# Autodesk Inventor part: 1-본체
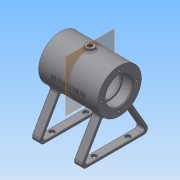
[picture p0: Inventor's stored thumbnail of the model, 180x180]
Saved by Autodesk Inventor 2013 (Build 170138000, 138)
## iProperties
Created: 2016-03
Part Number: 1-본체
Material: Generic
Document SubType Name: Modeling
Designer: Administrator
Density: 1 g/cm^3
Author: Administrator
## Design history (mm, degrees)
sketch "스케치1"
  geometry: C1 r 26 at (0, 0); 1 further point
  constraints: 1 centre point, 1 coincident
  dimensions: "d0" = 52 diameter of C1
extrude "돌출1" new body sketch "스케치1" distance "d2" = 70; taper "d3" = 0 deg
sketch "스케치2"
  geometry: C1 r 26 at (0, 0) reference; C2 r 16 at (0, 0)
  constraints: 1 centre point, 1 coincident
  dimensions: "d4" = 32 diameter of C2
extrude "돌출2" cut sketch "스케치2" distance "d6" = 12; taper "d7" = 0 deg
sketch "스케치3"
  geometry: C1 r 26 at (0, 0) reference; C2 r 16 at (0, 0)
  constraints: 1 centre point, 1 coincident
  dimensions: "d8" = 32 diameter of C2
extrude "돌출3" cut sketch "스케치3" distance "d10" = 12; taper "d11" = 0 deg
sketch "스케치4"
  geometry: C1 r 16 at (0, 0) reference; C2 r 14 at (0, 0)
  constraints: 1 centre point, 1 coincident
  dimensions: "d12" = 28 diameter of C2
extrude "돌출4" cut sketch "스케치4" distance "d14" = 2; taper "d15" = 0 deg
sketch "스케치5"
  geometry: C1 r 16 at (0, 0) reference; C2 r 14 at (0, 0)
  constraints: 1 centre point, 1 coincident
  dimensions: "d16" = 28 diameter of C2
extrude "돌출5" cut sketch "스케치5" distance "d18" = 2; taper "d19" = 0 deg
sketch "스케치6"
  geometry: C1 r 14 at (0, 0) reference; C2 r 21 at (0, 0)
  constraints: 1 centre point, 1 coincident
  dimensions: "d20" = 42 diameter of C2
extrude "돌출6" cut sketch "스케치6" distance "d22" = 42; taper "d23" = 0 deg
sketch "스케치7" dims "d24" = 42
  geometry: C1 r 16 at (0, 0) reference; C2 r 26 at (0, 0) reference; 2 further points
  constraints: 2 vertical alignment, 1 coincident, 2 other
hole "구멍1" sketch "스케치7" at (0, 21) diameter "d26" = 3.242; stored, may be unused: countersink angle "d30" = 90 deg, drill point angle "d32" = 118 deg; dims "d27" = 8, "d28" = 4, "d29" = 2, "d31" = 10
node "작업 평면1"
node "작업 평면2"
sketch "스케치8"
  geometry: L1 (26, 70)-(-26, 70) reference; L2 (-26, 0)-(26, 0) reference; L3 (-26, 0)-(-26, 70) reference; C1 r 5 at (0, 35); 3 further points
  constraints: 2 midpoint, 1 centre point, 1 horizontal alignment, 1 vertical alignment
  dimensions: "d37" = 10 diameter of C1
extrude "돌출7" join sketch "스케치8" stored distance "d39" = 10; taper "d40" = 0 deg
sketch "스케치9"
  geometry: C1 r 5 at (0, 0) reference; 2 further points
  constraints: 1 coincident
hole "구멍2" sketch "스케치9" at (0, 0) diameter "d41" = 5.188; stored, may be unused: countersink angle "d45" = 90 deg, drill point angle "d47" = 118 deg; dims "d42" = 10, "d43" = 4, "d44" = 2, "d46" = 10
node "작업 평면4"
  node "작업 평면3"
sketch "스케치10"
  geometry: L1 (-14.183, -21.791)-(-37.398, -62); L2 (-37.398, -62)-(37.398, -62); L3 (37.398, -62)-(14.183, -21.791); L4 (0, 0)-(0, -62); L5 (-16.613, -20)-(-42.594, -65); L6 (-42.594, -65)-(42.594, -65); L7 (42.594, -65)-(16.613, -20); A1 r 26 centre (0, 0) between (-16.613, -20) and (-14.183, -21.791) reference; 1 further point
  constraints: 14 end point, 4 point on circle, 1 horizontal, 1 midpoint, 1 perpendicular, 1 vertical alignment
  dimensions: "d52" = 3 distance between parallel lines of L1 L5; "d55" = 3 distance between parallel lines of L6 L2; "d56" = 3 distance between parallel lines of L7 L3; "d96" = 30 deg angle of L5 L4; "d98" = 60 deg angle of L7 L5; "d114" = 65 distance from line of L6 point (0, 0); "d115" = 45 vertical distance of L5.end L5.start
extrude "돌출8" join sketch "스케치10" distance "d58" = 10; taper "d59" = 0 deg
fillet "모깎기1" dims "d60" = 5
chamfer "모따기1" distance "d61" = 1; stored, may be unused: second distance "d62" = 2, angle "d63" = 45 deg
fillet "모깎기2" dims "d64" = 0.3
fillet "모깎기3" dims "d65" = 3
fillet "모깎기4" dims "d66" = 0.5
fillet "모깎기5" dims "d67" = 0.5
sketch "스케치11"
  geometry: L1 (-6.232, 0.5)-(-1.732, 0.5) reference; C1 r 3 at (12.202, -4.5); C2 r 3 at (52.202, -4.5); 2 further points
  constraints: 2 centre point, 1 equal radius, 1 horizontal alignment
  dimensions: "d68" = 6 diameter of C1; "d70" = 20 horizontal distance of C1.centre point (32.202, 55.5); "d71" = 5 distance from line of L1 C1.centre; "d72" = 40 distance of C2.centre C1.centre
extrude "돌출9" cut sketch "스케치11" stored distance "d73" = 10; taper "d74" = 0 deg
sketch "스케치12"
  geometry: L1 (0, 0)-(0, -26); L2 (0, 0)-(7.506, -28.012); 1 further point
  constraints: 4 end point, 1 vertical, 1 vertical alignment, 1 other
  dimensions: "d75" = 15 deg angle of L2 L1; "d76" = 29 distance of L1.start L2.end
node "작업 평면5"
fillet "모깎기6" dims "d88" = 2
fillet "모깎기7" dims "d89" = 3
node "작업 평면6"
sketch "스케치15"
  geometry: L1 (-26, 0)-(26, 0) reference; L2 (26, 0)-(26, 70) reference; 4 further points
  constraints: 2 midpoint, 1 horizontal alignment, 1 vertical alignment, 1 other
feature "엠보싱1" sketch "스케치15" dims "d0" = 52, "d92" = 0.5, "d93" = 0
sketch "스케치16"
  geometry: L1 (0, 0)-(0, -26); L2 (0, 0)-(7.506, -28.012); 1 further point
  constraints: 4 end point, 1 vertical, 1 vertical alignment, 1 other
  dimensions: "d99" = 15 deg angle of L2 L1; "d100" = 29 distance of L1.start L2.end
node "작업 평면7"
sketch "스케치17"
  geometry: L1 (26, -35)-(26, 35) reference; C1 r 6 at (0, 0); 2 further points
  constraints: 1 centre point, 1 horizontal alignment, 1 midpoint, 1 vertical alignment
  dimensions: "d101" = 12 diameter of C1
extrude "돌출11" join sketch "스케치17" stored distance "d103" = 10; taper "d104" = 0 deg
sketch "스케치18"
  geometry: C1 r 6 at (0, 0) reference; 2 further points
  constraints: 1 coincident
hole "구멍4" sketch "스케치18" at (0, 0) diameter "d105" = 5.188; stored, may be unused: countersink angle "d109" = 90 deg, drill point angle "d111" = 118 deg; dims "d106" = 10, "d107" = 4, "d108" = 2, "d110" = 10
fillet "모깎기9" dims "d112" = 2
fillet "모깎기10" dims "d113" = 3
node "솔리드1"
pattern_circular "원형 패턴1" dims angle "d34" = 360 deg
mirror "대칭1"
mirror "대칭2"
mirror "대칭3"
node "투영된 루프1"
other parameters: "d36" = 29, "d91" = -26
